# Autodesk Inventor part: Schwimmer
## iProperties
Created: 2005-10
Part Number: Schwimmer
Material: PVC rot
Document SubType Name: Modeling
Designer: rsc
Manufacturer: Standard
Standards Organization: Custom
Kanten: brechen
Oberflächen: Ra 3,2
Radien: 2
Toleranzen: ISO 2768 - m
Author: rsc
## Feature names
1. Drehung1 [Revolution]
